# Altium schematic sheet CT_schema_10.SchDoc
size 277 x 170 mm
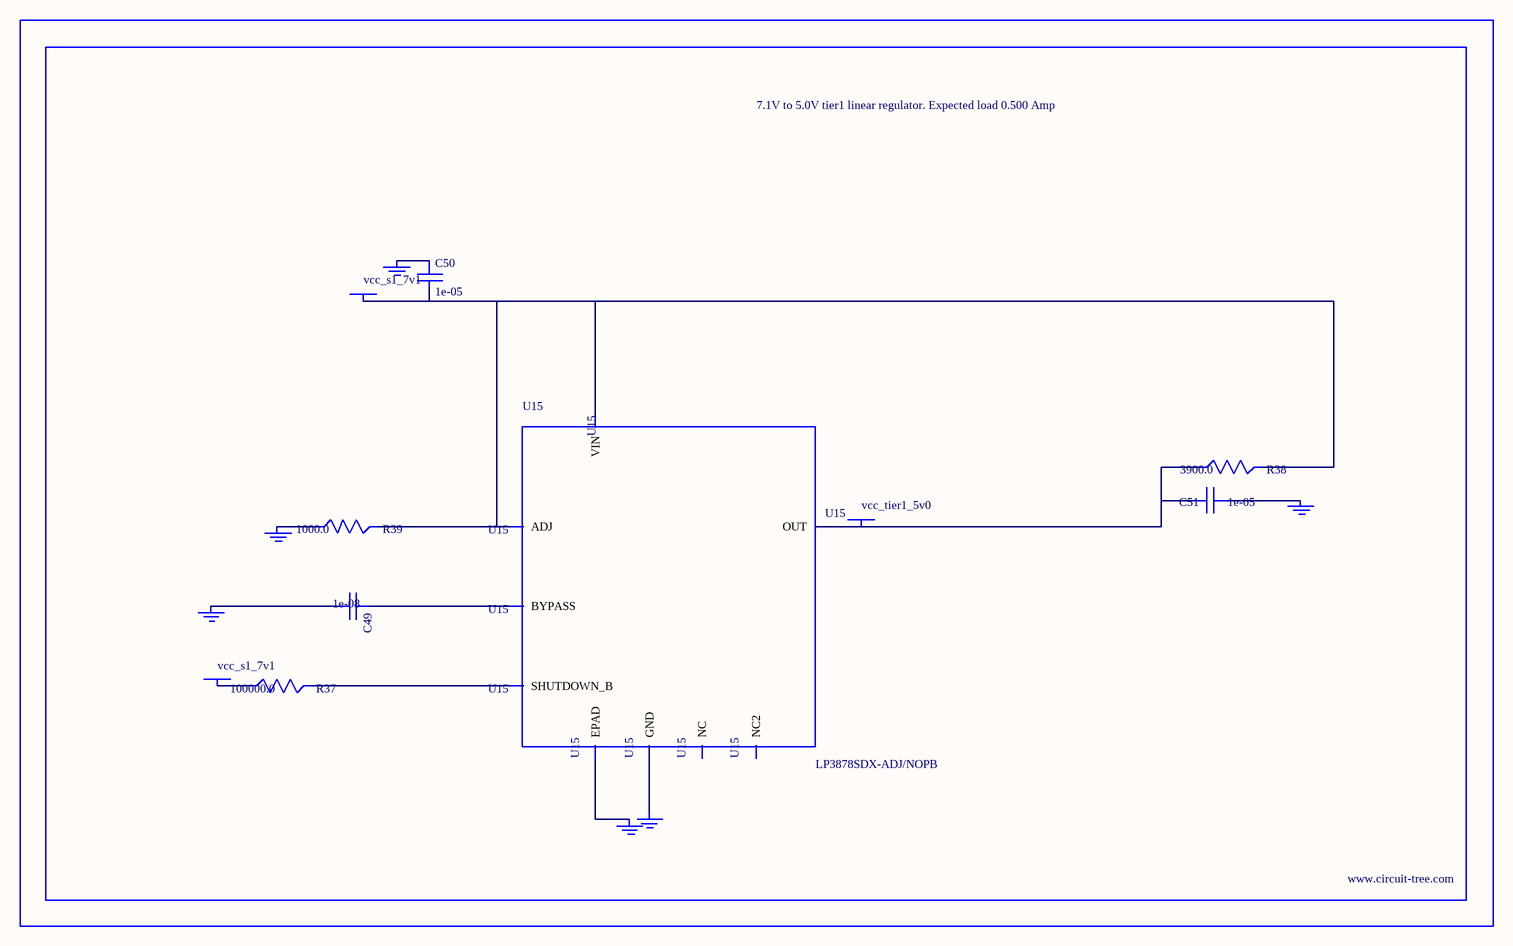
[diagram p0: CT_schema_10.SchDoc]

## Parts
BORDER9  (no value)
C49  1e-08  [C0402]
C50  1e-05  [C1206]
C51  1e-05  [C1210]
GND_INSTANCE_9_0  (no value)
GND_INSTANCE_9_1  (no value)
GND_INSTANCE_9_2  (no value)
GND_INSTANCE_9_3  (no value)
GND_INSTANCE_9_4  (no value)
GND_INSTANCE_9_5  (no value)
POWER_INSTANCE_9_0  vcc_s1_7v1
POWER_INSTANCE_9_1  vcc_s1_7v1
POWER_INSTANCE_9_2  vcc_tier1_5v0
R37  100000.0  [R0603]
R38  3900.0  [R0603]
R39  1000.0  [R0603]
U15  LP3878SDX-ADJ/NOPB  [WSON-8]

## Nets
NetC49_1: C49.1 U15.1(BYPASS)
NetC49_2: C49.2 GND_INSTANCE_9_0.0(GND)
NetC50_1: C50.1 GND_INSTANCE_9_1.0(GND)
NetC50_2: C50.2 POWER_INSTANCE_9_0.0(PWR) R38.2 R39.2 U15.4(VIN) U15.6(ADJ)
NetC51_1: C51.1 GND_INSTANCE_9_2.0(GND)
NetC51_2: C51.2 POWER_INSTANCE_9_2.0(PWR) R38.1 U15.5(OUT)
NetGND_INSTANCE_9_3_0: GND_INSTANCE_9_3.0(GND) R39.1
NetGND_INSTANCE_9_4_0: GND_INSTANCE_9_4.0(GND) U15.PAD(EPAD)
NetGND_INSTANCE_9_5_0: GND_INSTANCE_9_5.0(GND) U15.3(GND)
NetPOWER_INSTANCE_9_1_0: POWER_INSTANCE_9_1.0(PWR) R37.1
NetR37_2: R37.2 U15.8(SHUTDOWN_B)

Not connected (* = marked no-connect by the designer): U15 2(NC) 7(NC2)

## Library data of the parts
BORDER9 = BORDER_PAGE9
C49 = C0402C103K3RAC
C50 = C1206C106K3RACTU
C51 = GRM32DR61E106MA12L
GND_INSTANCE_9_0-GND_INSTANCE_9_5 = GND
POWER_INSTANCE_9_0-POWER_INSTANCE_9_2 = PWR
R37 = RC0603JR-07100KL
R38 = RC0603JR-073K9L
R39 = RC0603JR-071KL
